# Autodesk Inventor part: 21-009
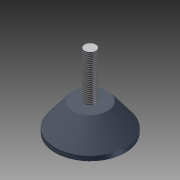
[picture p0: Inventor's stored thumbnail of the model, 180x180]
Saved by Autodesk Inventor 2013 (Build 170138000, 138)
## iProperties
Created: 2003-01
Part Number: 21-009
Vendor: PARKER IPS
Document SubType Name: Modeling
Designer: Autodesk, Inc.
Description: KNUCKLE FOOT 40, M8x65
Catalog Web Link: http://www.parker.com/ead/cm1.asp?cmid=809
Mass: 39.8452 g
Surface Area: 167.331 cm^2
Volume: 39.8452 cm^3
Density: 1 g/cm^3
Material: Allgemein
CAGE: 08JJ3
Dept. ID: Product Design
Description #2: ---
Finish #1: ---
Finish #2: ---
Material ID: ---
Project Number: ---
NEXT HIGHER ASSY 01: ---
Author: Autodesk, Inc.
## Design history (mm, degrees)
derived "21-0xx Knuckle Foot.ipt"
body "Solid1"
tag "TaggingFeature2"
feature "Solid1::21-0xx Knuckle Foot.ipt" dims "ScaleForDerivedMember" = 10
